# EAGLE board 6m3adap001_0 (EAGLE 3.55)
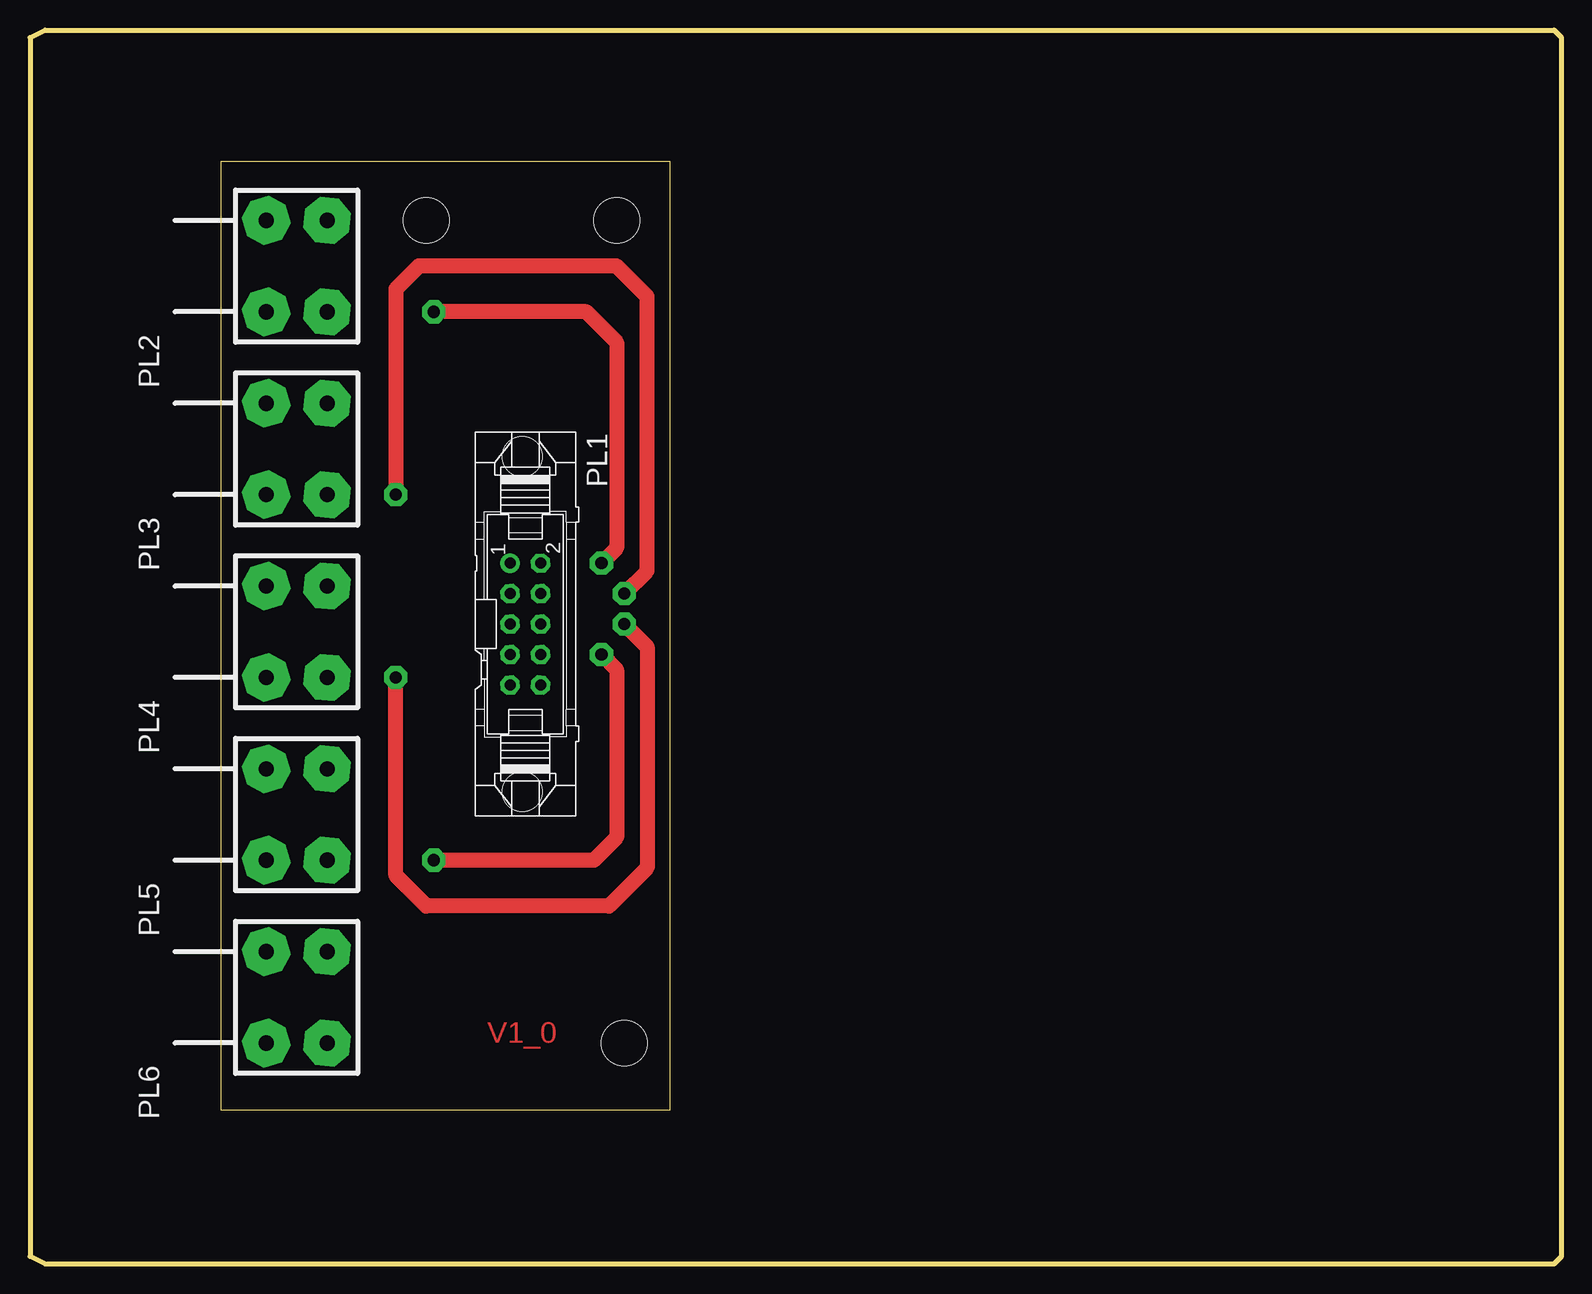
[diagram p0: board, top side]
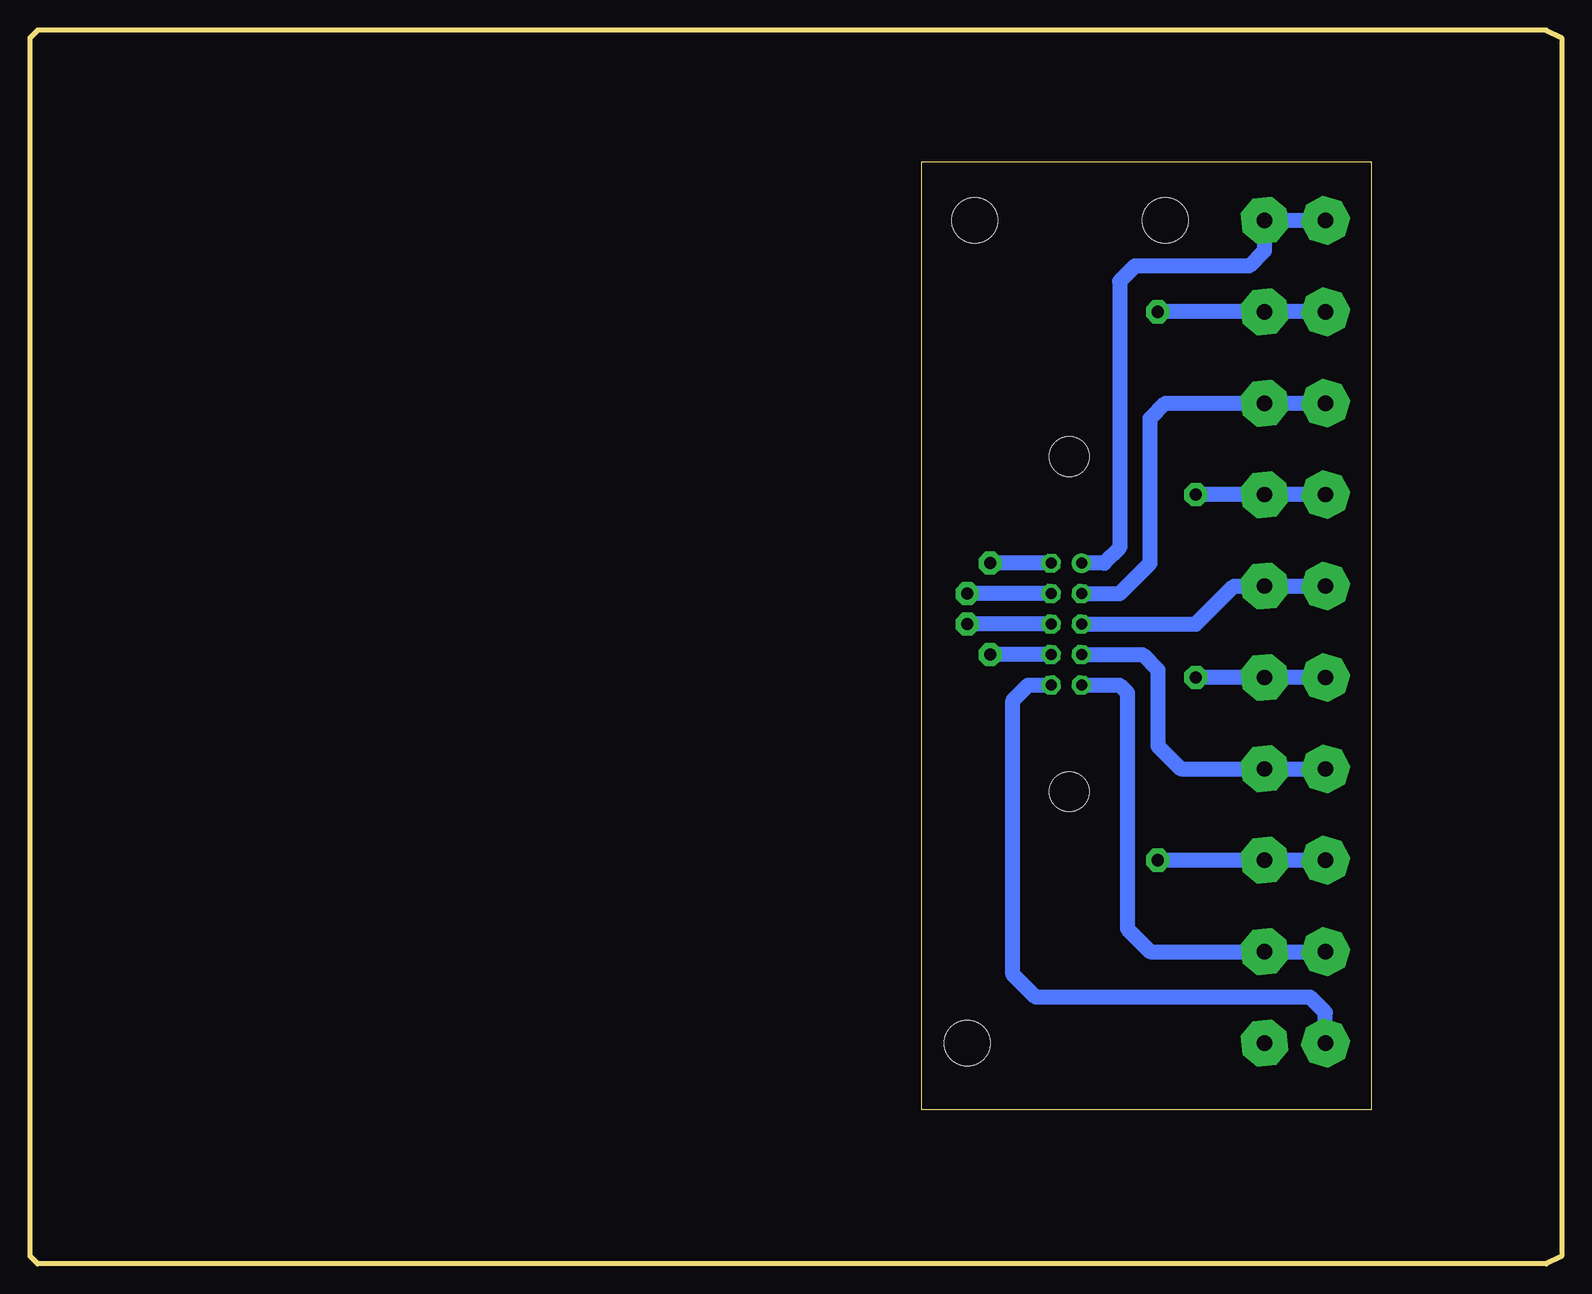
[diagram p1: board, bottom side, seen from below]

Size 127.64 x 102.87 mm. Coordinates in mm from the lower left corner, seen from the top.
Outline: 53.34,12.86 53.34,91.91 15.88,91.91 15.88,12.86 53.34,12.86
Outline: 0,0.63 1.27,0 127,0 127.64,0.63 127.64,102.23 127,102.87 1.27,102.87 0,102.23 0,0.63
Copper layers used: Top, Bottom
Holes 3.81 mm at 33.02,87 49.53,18.41 48.9,87
vRestrict: area 69.9,50.8 to 94,74.9

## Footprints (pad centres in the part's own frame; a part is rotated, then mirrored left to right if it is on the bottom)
V = drill 0.914 pad 1.6 round:  -5.08,-1.27 | drill 0.914 pad 1.6 octagon:  -5.08,1.27;  -2.54,-1.27;  -2.54,1.27;  0,-1.27;  0,1.27;  2.54,-1.27;  2.54,1.27;  5.08,-1.27;  5.08,1.27 | hole 3.302: 13.97,-0.254; -13.97,-0.254
3MM = drill 1.27 pad 3.81 octagon:  0,0;  7.62,0;  0,-5.08;  7.62,-5.08

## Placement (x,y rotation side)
PL1  10V  [V]  41.27,53.34 270 top
PL2  6_3MM  [3MM]  19.68,79.38 90 top
PL3  6_3MM  [3MM]  19.68,64.14 90 top
PL4  6_3MM  [3MM]  19.68,48.89 90 top
PL5  6_3MM  [3MM]  19.68,33.66 90 top
PL6  6_3MM  [3MM]  19.68,18.41 90 top

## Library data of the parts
PL1 = pinh-v
PL2-PL6 = andit4at

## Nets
N$1: PL1. PL6.
N$2: PL1. PL6.
N$3: PL1. PL5.
N$4: PL1. PL5.
N$5: PL1. PL4.
N$6: PL1. PL4.
N$7: PL1. PL3.
N$9: PL1. PL3.
N$10: PL1. PL2.
N$11: PL1. PL2.

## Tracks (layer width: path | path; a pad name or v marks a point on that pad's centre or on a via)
N$1
  Bottom 1.27: 19.68,18.41 19.68,20.95 20.95,22.23 43.81,22.23 45.72,24.13 45.72,46.99 44.45,48.26 PL1.
N$2
  Bottom 1.27: 40,48.26 36.83,48.26 36.2,47.62 36.2,27.94 34.29,26.04 19.68,26.04
N$3  (via drill 1.02 pad 1.93)
  Top 1.27: v47.62,50.8 48.9,49.53 48.9,35.56 46.99,33.66 v33.66,33.66
  Bottom 1.27: 19.68,33.66 v33.66,33.66 | 42.55,50.8 v47.62,50.8
N$4
  Bottom 1.27: 40,50.8 34.92,50.8 33.66,49.53 33.66,43.18 31.75,41.27 19.68,41.27
N$5  (via drill 1.02 pad 1.93)
  Top 1.27: v49.53,53.34 51.44,51.44 51.44,33.02 48.26,29.84 33.02,29.84 30.48,32.38 v30.48,48.89
  Bottom 1.27: 19.68,48.89 v30.48,48.89 | 42.55,53.34 v49.53,53.34
N$6
  Bottom 1.27: 40,53.34 30.48,53.34 27.3,56.52 19.68,56.52
N$7  (via drill 1.02 pad 1.93)
  Top 1.27: v49.53,55.88 51.44,57.78 51.44,80.64 48.9,83.19 32.39,83.19 30.48,81.28 v30.48,64.14
  Bottom 1.27: 19.68,64.14 v30.48,64.14 | 42.55,55.88 v49.53,55.88
N$9
  Bottom 1.27: 40,55.88 36.83,55.88 34.29,58.42 34.29,70.48 33.02,71.75 19.68,71.75
N$10  (via drill 1.02 pad 1.93)
  Top 1.27: v47.62,58.42 48.9,59.69 48.9,76.84 46.36,79.38 v33.66,79.38
  Bottom 1.27: 19.68,79.38 v33.66,79.38 | 42.55,58.42 v47.62,58.42
N$11
  Bottom 1.27: 19.68,87 PL2. 24.77,84.45 26.04,83.19 35.56,83.19 36.83,81.92 36.83,59.69 38.1,58.42 40,58.42

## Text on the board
Top: V1_0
